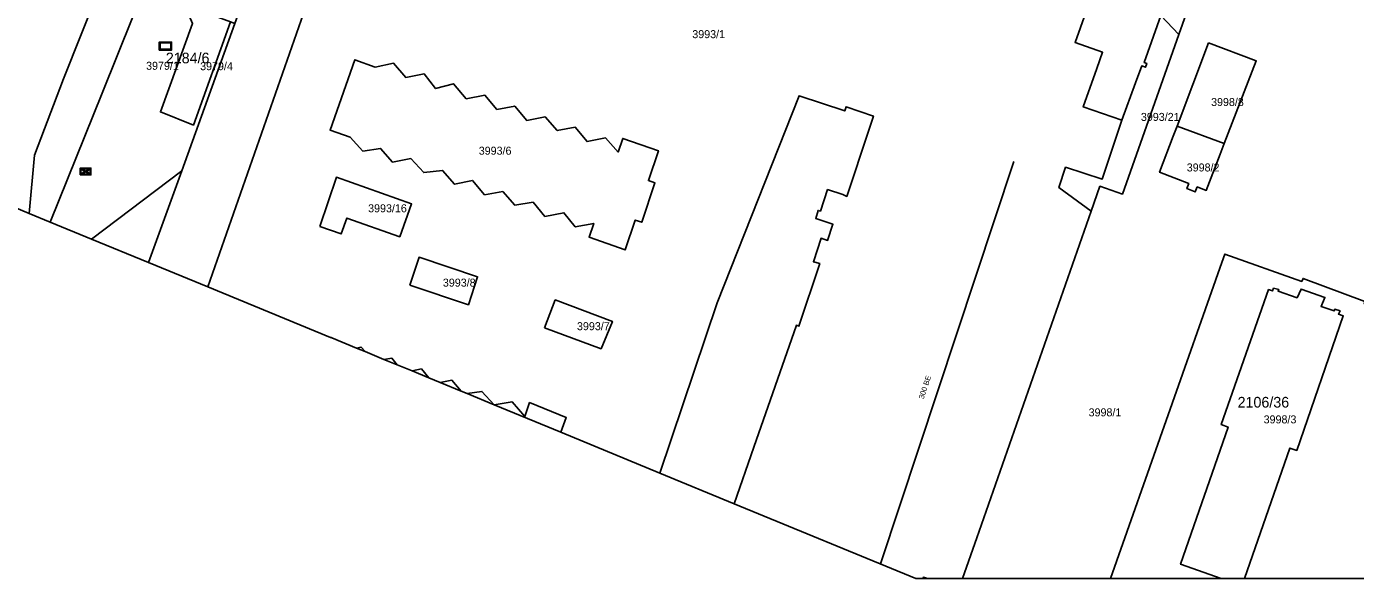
# Model space of a CAD drawing. Extents: x -570104 to -569328, y -1087857 to -1087418.
# Drawn here: x -569780.6 to -569531.5, y -1087857 to -1087753.5 of the extents above; entities that cross this region are included whole.
import ezdxf

# ---------------------------------------------------------------- set-up
doc = ezdxf.new("R2010")
doc.units = 0
for name, color, linetype in [('Adresní místo-text', 7, 'Continuous'), ('Dešťová vpusť', 7, 'Continuous'), ('Kanalizační přípojka', 7, 'Continuous'), ('Lapač olejů', 7, 'Continuous'), ('Parcela-polygon', 7, 'Continuous'), ('Parcela-text', 7, 'Continuous'), ('Popis přípojky', 7, 'Continuous')]:
    doc.layers.add(name, color=color, linetype=linetype)

msp = doc.modelspace()

# ---------------------------------------------------------------- linework, layer by layer
at = {"layer": 'Dešťová vpusť'}
for points in [[(-569770.5, -1087781.33), (-569770.5, -1087780.05), (-569768.5, -1087780.05), (-569768.5, -1087781.33), (-569770.5, -1087781.33)], [(-569769.61, -1087780.68), (-569770.37, -1087780.23), (-569770.37, -1087781.14), (-569769.61, -1087780.68)], [(-569769.48, -1087780.76), (-569770.25, -1087781.21), (-569768.72, -1087781.21), (-569769.48, -1087780.76)], [(-569769.48, -1087780.61), (-569768.74, -1087780.17), (-569770.23, -1087780.17), (-569769.48, -1087780.61)], [(-569768.63, -1087781.12), (-569768.63, -1087780.25), (-569769.36, -1087780.68), (-569768.63, -1087781.12)]]:
    msp.add_lwpolyline(points, dxfattribs=at)
at = {"layer": 'Kanalizační přípojka'}
msp.add_lwpolyline([(-569595.53, -1087778.8), (-569620.53, -1087854.29)], dxfattribs=at)
at = {"layer": 'Lapač olejů'}
for points in [[(-569755.7, -1087757.92), (-569755.7, -1087756.44), (-569753.4, -1087756.44), (-569753.4, -1087757.92), (-569755.7, -1087757.92)], [(-569753.54, -1087757.78), (-569753.54, -1087756.59), (-569755.55, -1087756.59), (-569755.55, -1087757.78), (-569753.54, -1087757.78)]]:
    msp.add_lwpolyline(points, dxfattribs=at)
at = {"layer": 'Parcela-polygon'}
for p, q in [((-569800.18, -1087780.26), (-569780.06, -1087788.55)), ((-569780.06, -1087788.55), (-569776.13, -1087790.17)), ((-569776.13, -1087790.17), (-569768.4, -1087793.36)), ((-569768.4, -1087793.36), (-569757.72, -1087797.76)), ((-569757.72, -1087797.76), (-569746.61, -1087802.34)), ((-569746.61, -1087802.34), (-569723.58, -1087811.83)), ((-569723.58, -1087811.83), (-569723.35, -1087811.92)), ((-569723.35, -1087811.92), (-569718.75, -1087813.82)), ((-569718.75, -1087813.82), (-569717.14, -1087814.48)), ((-569717.14, -1087814.48), (-569713.59, -1087815.94)), ((-569713.59, -1087815.94), (-569711.13, -1087816.96)), ((-569711.13, -1087816.96), (-569708.33, -1087818.11)), ((-569708.33, -1087818.11), (-569705.21, -1087819.4)), ((-569705.21, -1087819.4), (-569703.03, -1087820.3)), ((-569703.03, -1087820.3), (-569699.11, -1087821.91)), ((-569699.11, -1087821.91), (-569698.01, -1087822.36)), ((-569698.01, -1087822.36), (-569692.95, -1087824.45)), ((-569692.95, -1087824.45), (-569692.91, -1087824.47)), ((-569692.91, -1087824.47), (-569680.43, -1087829.61)), ((-569680.43, -1087829.61), (-569661.87, -1087837.26)), ((-569661.87, -1087837.26), (-569647.94, -1087843)), ((-569647.94, -1087843), (-569613.91, -1087857.02)), ((-569613.91, -1087857.02), (-569612.59, -1087857.02)), ((-569612.59, -1087857.02), (-569611.75, -1087857.02)), ((-569611.75, -1087857.02), (-569605.18, -1087857.02)), ((-569605.18, -1087857.02), (-569577.45, -1087857.02)), ((-569577.45, -1087857.02), (-569556.69, -1087857.02)), ((-569556.69, -1087857.02), (-569552.33, -1087857.02)), ((-569552.33, -1087857.02), (-569526.52, -1087857.02))]:
    msp.add_line(p, q, dxfattribs=at)
for points in [[(-569746.61, -1087802.34), (-569724.3, -1087738.5), (-569720.63, -1087739.3), (-569710.72, -1087711.45), (-569706.1, -1087706.13), (-569677.75, -1087620.8), (-569675.24, -1087615.77), (-569677.5, -1087614.66), (-569709.27, -1087708.71), (-569712.54, -1087708.01), (-569722.07, -1087703.64), (-569688.74, -1087606.97), (-569723.77, -1087703.85), (-569734.36, -1087733.15), (-569741.51, -1087752.92), (-569751.5, -1087780.56), (-569757.72, -1087797.76)], [(-569776.13, -1087790.17), (-569766.4, -1087766), (-569746.5, -1087716.3), (-569739.39, -1087698.97), (-569735.85, -1087690.34), (-569736.88, -1087689.77), (-569737.61, -1087689.09), (-569739.04, -1087686.03), (-569740.52, -1087682.49), (-569740.88, -1087681.36), (-569747.16, -1087696.87), (-569753.65, -1087713.04), (-569773.64, -1087763.31), (-569779.09, -1087777.66), (-569780.06, -1087788.55)], [(-569577.45, -1087857.02), (-569556.58, -1087797.77), (-569556.02, -1087796.19), (-569541.61, -1087801.32), (-569541.34, -1087800.75), (-569529.77, -1087805.11), (-569529.88, -1087805.5), (-569510.5, -1087812.41), (-569480.79, -1087729.63), (-569489.42, -1087709.06), (-569489.76, -1087708.24), (-569539.35, -1087682.53), (-569546.41, -1087703.53), (-569564.62, -1087755), (-569575.22, -1087784.93), (-569579.43, -1087783.46), (-569581.07, -1087788.14), (-569602.51, -1087849.39), (-569605.18, -1087857.02)], [(-569768.4, -1087793.36), (-569751.5, -1087780.56), (-569741.51, -1087752.92), (-569742.34, -1087752.62), (-569749.29, -1087772), (-569755.49, -1087769.51), (-569749.45, -1087752.96), (-569750.55, -1087750.53), (-569749.27, -1087746.98), (-569746.92, -1087740.49), (-569744.26, -1087729.61), (-569742.5, -1087722.41), (-569738.57, -1087711.21), (-569737.69, -1087699.63), (-569739.39, -1087698.97), (-569746.5, -1087716.3), (-569766.4, -1087766), (-569776.13, -1087790.17)], [(-569567.99, -1087751.44), (-569564.62, -1087755), (-569546.41, -1087703.53)], [(-569780.06, -1087788.55), (-569779.09, -1087777.66), (-569773.64, -1087763.31), (-569753.65, -1087713.04)], [(-569605.18, -1087857.02), (-569602.51, -1087849.39), (-569581.07, -1087788.14), (-569587.15, -1087783.68), (-569585.86, -1087779.89), (-569578.99, -1087782.13), (-569575.3, -1087771.06), (-569582.54, -1087768.59), (-569580, -1087761.41), (-569578.91, -1087758.34), (-569584.06, -1087756.52), (-569573.68, -1087727.24)], [(-569724.3, -1087738.5), (-569746.61, -1087802.34)], [(-569559.08, -1087756.58), (-569550.13, -1087759.94), (-569556.12, -1087775.45), (-569556.88, -1087777.44), (-569559.51, -1087784.25), (-569561.18, -1087783.6), (-569561.55, -1087784.53), (-569563.13, -1087783.9), (-569562.77, -1087782.97), (-569568.24, -1087780.83), (-569565.7, -1087774.1), (-569564.97, -1087772.17), (-569559.08, -1087756.58)], [(-569692.47, -1087769.07), (-569689.08, -1087768.42), (-569686.84, -1087771.11), (-569683.4, -1087770.44), (-569681.13, -1087773.02), (-569677.74, -1087772.39), (-569675.53, -1087775.1), (-569672.1, -1087774.4), (-569669.72, -1087777.06), (-569668.85, -1087774.48), (-569662.17, -1087776.8), (-569664.04, -1087782.4), (-569662.81, -1087782.81), (-569665.28, -1087790.22), (-569666.51, -1087789.81), (-569668.38, -1087795.41), (-569675.16, -1087793.01), (-569674.29, -1087790.45), (-569677.75, -1087791.08), (-569679.88, -1087788.43), (-569683.43, -1087789.11), (-569685.64, -1087786.46), (-569689.07, -1087787.01), (-569691.34, -1087784.47), (-569694.72, -1087785.07), (-569697.02, -1087782.37), (-569700.4, -1087783.1), (-569702.6, -1087780.51), (-569706.13, -1087780.89), (-569708.54, -1087778.29), (-569711.99, -1087778.96), (-569714.23, -1087776.36), (-569717.55, -1087776.91), (-569719.94, -1087774.23), (-569723.69, -1087772.93), (-569719.07, -1087759.73), (-569715.21, -1087761.12), (-569711.78, -1087760.39), (-569709.5, -1087763.04), (-569706.06, -1087762.38), (-569703.91, -1087765.14), (-569700.53, -1087764.25), (-569698.18, -1087767.06), (-569694.68, -1087766.41), (-569692.47, -1087769.07)], [(-569661.87, -1087837.26), (-569651.14, -1087805.31), (-569635.79, -1087766.5), (-569627.23, -1087769.34), (-569626.98, -1087768.57), (-569621.86, -1087770.32), (-569622.75, -1087772.93), (-569626.85, -1087785.38), (-569627.61, -1087785.03), (-569630.46, -1087784.08), (-569631.8, -1087788.13), (-569632.23, -1087787.99), (-569632.68, -1087789.51), (-569629.46, -1087790.58), (-569630.47, -1087793.63), (-569631.66, -1087793.23), (-569633.11, -1087797.62), (-569631.92, -1087797.98), (-569635.82, -1087809.71), (-569636.29, -1087809.54), (-569644.28, -1087832.38), (-569647.94, -1087843)], [(-569647.94, -1087843), (-569644.28, -1087832.38), (-569636.29, -1087809.54), (-569635.82, -1087809.71), (-569631.92, -1087797.98), (-569633.11, -1087797.62), (-569631.66, -1087793.23), (-569630.47, -1087793.63), (-569629.46, -1087790.58), (-569632.68, -1087789.51), (-569632.23, -1087787.99), (-569631.8, -1087788.13), (-569630.46, -1087784.08), (-569627.61, -1087785.03), (-569626.85, -1087785.38), (-569622.75, -1087772.93), (-569621.86, -1087770.32), (-569626.98, -1087768.57), (-569627.23, -1087769.34), (-569635.79, -1087766.5), (-569651.14, -1087805.31), (-569661.87, -1087837.26)], [(-569757.72, -1087797.76), (-569751.5, -1087780.56), (-569768.4, -1087793.36)], [(-569725.64, -1087791.01), (-569722.51, -1087781.78), (-569708.43, -1087786.79), (-569710.63, -1087792.95), (-569720.54, -1087789.42), (-569721.6, -1087792.41), (-569725.64, -1087791.01)], [(-569708.75, -1087802.04), (-569707.02, -1087796.79), (-569696.05, -1087800.43), (-569697.75, -1087805.7), (-569708.75, -1087802.04)], [(-569526.52, -1087857.02), (-569514.85, -1087824.53), (-569510.5, -1087812.41), (-569529.88, -1087805.5), (-569529.77, -1087805.11), (-569541.34, -1087800.75), (-569541.61, -1087801.32), (-569556.02, -1087796.19), (-569556.58, -1087797.77), (-569577.45, -1087857.02)], [(-569556.69, -1087857.02), (-569564.32, -1087854.37), (-569555.39, -1087828.63), (-569556.68, -1087828.17), (-569547.82, -1087802.83), (-569547.09, -1087803.11), (-569546.89, -1087802.59), (-569545.9, -1087802.8), (-569546.02, -1087803.13), (-569542.46, -1087804.39), (-569541.72, -1087802.75), (-569537.25, -1087804.3), (-569537.98, -1087805.99), (-569535.53, -1087806.86), (-569535.41, -1087806.53), (-569534.41, -1087806.83), (-569534.73, -1087807.44), (-569533.83, -1087807.75), (-569542.55, -1087833.02), (-569543.83, -1087832.57), (-569552.33, -1087857.02)], [(-569552.33, -1087857.02), (-569543.83, -1087832.57), (-569542.55, -1087833.02), (-569533.83, -1087807.75), (-569534.73, -1087807.44), (-569534.41, -1087806.83), (-569535.41, -1087806.53), (-569535.53, -1087806.86), (-569537.98, -1087805.99), (-569537.25, -1087804.3), (-569541.72, -1087802.75), (-569542.46, -1087804.39), (-569546.02, -1087803.13), (-569545.9, -1087802.8), (-569546.89, -1087802.59), (-569547.09, -1087803.11), (-569547.82, -1087802.83), (-569556.68, -1087828.17), (-569555.39, -1087828.63), (-569564.32, -1087854.37), (-569556.69, -1087857.02)], [(-569683.52, -1087810.03), (-569681.49, -1087804.77), (-569670.77, -1087808.81), (-569672.91, -1087813.93), (-569683.52, -1087810.03)], [(-569723.58, -1087811.83), (-569723.45, -1087811.81), (-569723.35, -1087811.92)], [(-569723.35, -1087811.92), (-569723.45, -1087811.81), (-569723.58, -1087811.83)], [(-569718.75, -1087813.82), (-569717.87, -1087813.63), (-569717.14, -1087814.48)], [(-569717.14, -1087814.48), (-569717.87, -1087813.63), (-569718.75, -1087813.82)], [(-569713.59, -1087815.94), (-569712.1, -1087815.72), (-569711.13, -1087816.96)], [(-569711.13, -1087816.96), (-569712.1, -1087815.72), (-569713.59, -1087815.94)], [(-569708.33, -1087818.11), (-569706.56, -1087817.72), (-569705.21, -1087819.4)], [(-569705.21, -1087819.4), (-569706.56, -1087817.72), (-569708.33, -1087818.11)], [(-569703.03, -1087820.3), (-569700.87, -1087819.84), (-569699.11, -1087821.91)], [(-569699.11, -1087821.91), (-569700.87, -1087819.84), (-569703.03, -1087820.3)], [(-569698.01, -1087822.36), (-569695.22, -1087821.94), (-569692.95, -1087824.45)], [(-569692.95, -1087824.45), (-569695.22, -1087821.94), (-569698.01, -1087822.36)], [(-569692.91, -1087824.47), (-569689.58, -1087823.87), (-569687.18, -1087826.63), (-569686.3, -1087824.03), (-569679.43, -1087826.84), (-569680.43, -1087829.61)], [(-569680.43, -1087829.61), (-569679.43, -1087826.84), (-569686.3, -1087824.03), (-569687.18, -1087826.63), (-569689.58, -1087823.87), (-569692.91, -1087824.47)], [(-569612.59, -1087857.02), (-569612.51, -1087856.78), (-569611.75, -1087857.02)], [(-569611.75, -1087857.02), (-569612.51, -1087856.78), (-569612.59, -1087857.02)]]:
    msp.add_lwpolyline(points, dxfattribs=at)
for points in [[(-569584.06, -1087756.52), (-569578.91, -1087758.34), (-569580, -1087761.41), (-569582.54, -1087768.59), (-569575.3, -1087771.06), (-569572.74, -1087764.06), (-569571.59, -1087760.9), (-569570.89, -1087761.14), (-569570.64, -1087760.43), (-569571.11, -1087760.27), (-569567.99, -1087751.44), (-569563.11, -1087737.53), (-569562.64, -1087737.69), (-569560.6, -1087731.68), (-569564.53, -1087730.3), (-569564.66, -1087722.48), (-569565.06, -1087722.48), (-569565.06, -1087722.67), (-569574.1, -1087719.21), (-569573.99, -1087718.9), (-569574.35, -1087718.78), (-569576.95, -1087725.98), (-569573.68, -1087727.24)], [(-569749.27, -1087746.98), (-569750.55, -1087750.53), (-569749.45, -1087752.96), (-569755.49, -1087769.51), (-569749.29, -1087772), (-569742.34, -1087752.62), (-569745.38, -1087751.52), (-569744.9, -1087750.21), (-569746.03, -1087749.8), (-569745.52, -1087748.39)], [(-569578.99, -1087782.13), (-569585.86, -1087779.89), (-569587.15, -1087783.68), (-569581.07, -1087788.14), (-569579.43, -1087783.46), (-569575.22, -1087784.93), (-569564.62, -1087755), (-569567.99, -1087751.44), (-569571.11, -1087760.27), (-569570.64, -1087760.43), (-569570.89, -1087761.14), (-569571.59, -1087760.9), (-569572.74, -1087764.06), (-569575.3, -1087771.06)], [(-569559.08, -1087756.58), (-569564.97, -1087772.17), (-569556.12, -1087775.45), (-569550.13, -1087759.94)], [(-569692.47, -1087769.07), (-569694.68, -1087766.41), (-569698.18, -1087767.06), (-569700.53, -1087764.25), (-569703.91, -1087765.14), (-569706.06, -1087762.38), (-569709.5, -1087763.04), (-569711.78, -1087760.39), (-569715.21, -1087761.12), (-569719.07, -1087759.73), (-569723.69, -1087772.93), (-569719.94, -1087774.23), (-569717.55, -1087776.91), (-569714.23, -1087776.36), (-569711.99, -1087778.96), (-569708.54, -1087778.29), (-569706.13, -1087780.89), (-569702.6, -1087780.51), (-569700.4, -1087783.1), (-569697.02, -1087782.37), (-569694.72, -1087785.07), (-569691.34, -1087784.47), (-569689.07, -1087787.01), (-569685.64, -1087786.46), (-569683.43, -1087789.11), (-569679.88, -1087788.43), (-569677.75, -1087791.08), (-569674.29, -1087790.45), (-569675.16, -1087793.01), (-569668.38, -1087795.41), (-569666.51, -1087789.81), (-569665.28, -1087790.22), (-569662.81, -1087782.81), (-569664.04, -1087782.4), (-569662.17, -1087776.8), (-569668.85, -1087774.48), (-569669.72, -1087777.06), (-569672.1, -1087774.4), (-569675.53, -1087775.1), (-569677.74, -1087772.39), (-569681.13, -1087773.02), (-569683.4, -1087770.44), (-569686.84, -1087771.11), (-569689.08, -1087768.42)], [(-569568.24, -1087780.83), (-569562.77, -1087782.97), (-569563.13, -1087783.9), (-569561.55, -1087784.53), (-569561.18, -1087783.6), (-569559.51, -1087784.25), (-569556.88, -1087777.44), (-569556.12, -1087775.45), (-569564.97, -1087772.17), (-569565.7, -1087774.1)], [(-569725.64, -1087791.01), (-569721.6, -1087792.41), (-569720.54, -1087789.42), (-569710.63, -1087792.95), (-569708.43, -1087786.79), (-569722.51, -1087781.78)], [(-569708.75, -1087802.04), (-569697.75, -1087805.7), (-569696.05, -1087800.43), (-569707.02, -1087796.79)], [(-569683.52, -1087810.03), (-569672.91, -1087813.93), (-569670.77, -1087808.81), (-569681.49, -1087804.77)]]:
    msp.add_lwpolyline(points, close=True, dxfattribs=at)

# ---------------------------------------------------------------- texts
at = {"layer": 'Adresní místo-text'}
for s, p in [('2184/6', (-569754.47, -1087760.41)), ('2106/36', (-569553.62, -1087824.97))]:
    msp.add_text(s, height=2, dxfattribs=at).set_placement(p)
at = {"layer": 'Parcela-text'}
for s, p in [('3993/1', (-569655.81, -1087755.69)), ('3979/1', (-569758.17, -1087761.62)), ('3979/4', (-569748.04, -1087761.7)), ('3998/8', (-569558.59, -1087768.42)), ('3993/21', (-569571.74, -1087771.21)), ('3993/6', (-569695.83, -1087777.55)), ('3998/2', (-569563.15, -1087780.69)), ('3993/16', (-569716.56, -1087788.35)), ('3993/8', (-569702.55, -1087802.29)), ('3993/7', (-569677.42, -1087810.46)), ('3998/1', (-569581.54, -1087826.62)), ('3998/3', (-569548.74, -1087827.94))]:
    msp.add_text(s, height=1.5, dxfattribs=at).set_placement(p)
at = {"layer": 'Popis přípojky'}
msp.add_text('300 BE', height=1, rotation=71.6794, dxfattribs=at).set_placement((-569612.46, -1087823.46))

doc.saveas('drawing.dxf')
